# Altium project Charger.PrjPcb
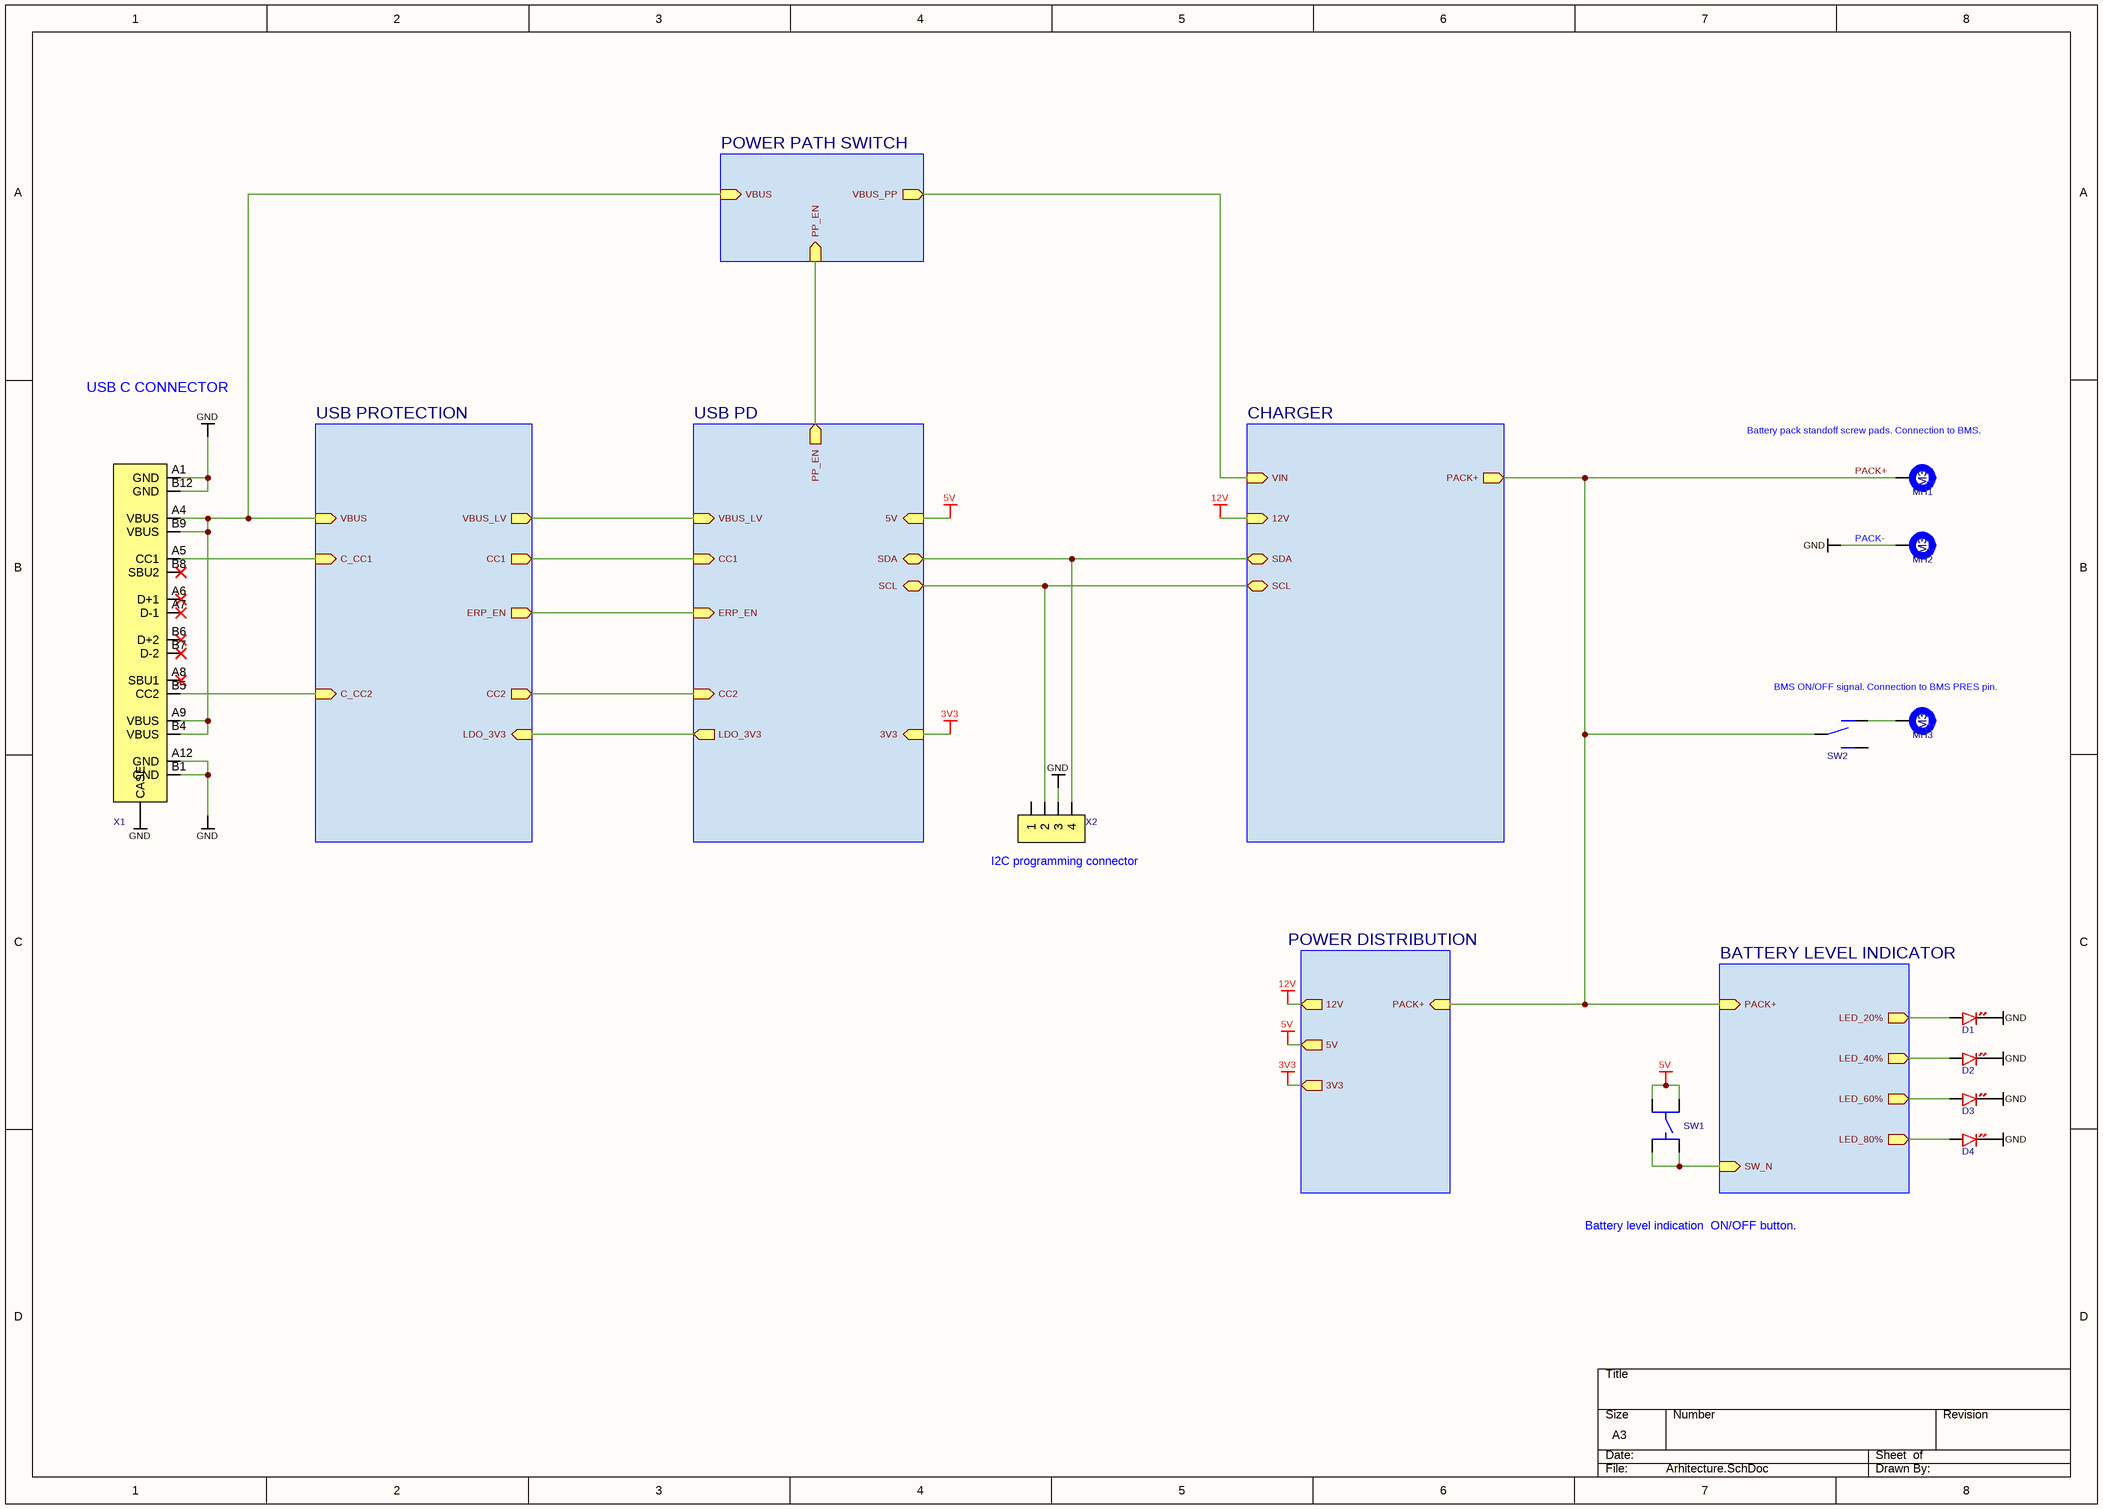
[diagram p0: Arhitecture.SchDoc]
7 sheets, 202 parts. Net scope: hierarchical (ports join the sheet entries above them; power ports are global).
Board file: PCB Charger.PcbDoc
Sheets:
  Arhitecture.SchDoc
    CHARGER = Charger.SchDoc
    POWER DISTRIBUTION = Power distribution.SchDoc
    USB PD = USB PD.SchDoc
    USB PROTECTION = USB protection.SchDoc
    BATTERY LEVEL INDICATOR = Battery level indicator.SchDoc
    POWER PATH SWITCH = Power path switch.SchDoc

## Sheet Arhitecture.SchDoc
size A3; SheetNumber: 1; SheetTotal: 7

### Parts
D1  XL-1608SURC-06  [DIODE_0603]  (value not drawn)
D2  XL-1608SURC-06  [DIODE_0603]  (value not drawn)
D3  XL-1608SURC-06  [DIODE_0603]  (value not drawn)
D4  XL-1608SURC-06  [DIODE_0603]  (value not drawn)
MH1  Hole size: M3  [M3 Plated]  (hidden comment: M?)  (no BOM)
MH2  Hole size: M3  [M3 Plated]  (hidden comment: M?)  (no BOM)
MH3  Hole size: M3  [M3 Plated]  (hidden comment: M?)  (no BOM)
SW1  TS4560TP  [TS4560TP]  (value not drawn)
SW2  SS-3235S-L3  [SS-3235S-L3]  (value not drawn)
X1  TYPE-C 16P LTH6.8  [TYPE-C 16P LTH6.8]  (value not drawn)
X2  B4B-PH-K-S(LF)(SN)  [B4B-PH-K-S(LF)(SN)]  (value not drawn)

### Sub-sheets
BATTERY LEVEL INDICATOR = Battery level indicator.SchDoc: PACK+ (in), SW_N (in), LED_20% (out), LED_40% (out), LED_60% (out), LED_80% (out)
CHARGER = Charger.SchDoc: PACK+ (out), VIN (in), SDA (bidir), SCL (bidir), 12V (in)
POWER DISTRIBUTION = Power distribution.SchDoc: PACK+ (in), 12V (out), 5V (out), 3V3 (out)
POWER PATH SWITCH = Power path switch.SchDoc: VBUS (in), VBUS_PP (out), PP_EN (in)
USB PD = USB PD.SchDoc: VBUS_LV (in), ERP_EN (in), CC1 (in), LDO_3V3 (out), SDA (bidir), SCL (bidir), 5V (in), 3V3 (in), CC2 (in), PP_EN (out)
USB PROTECTION = USB protection.SchDoc: VBUS (in), C_CC1 (in), C_CC2 (in), VBUS_LV (out), ERP_EN (out), CC1 (out), LDO_3V3 (in), CC2 (out)

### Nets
3V3: sheet POWER DISTRIBUTION/3V3, sheet USB PD/3V3
5V: SW1.1 SW1.2 ; sheet POWER DISTRIBUTION/5V, sheet USB PD/5V
5V_SoC: SW1.3 SW1.4 ; sheet BATTERY LEVEL INDICATOR/SW_N
12V: sheet CHARGER/12V, sheet POWER DISTRIBUTION/12V
GND: D1.K D2.K D3.K D4.K MH2.1 X1.A1(GND) X1.A12(GND) X1.B1(GND) X1.B12(GND) X1.CASE X2.3
LDO_3V3: sheet USB PD/LDO_3V3, sheet USB PROTECTION/LDO_3V3
C_CC1: X1.A5(CC1) ; sheet USB PROTECTION/C_CC1
C_CC2: X1.B5(CC2) ; sheet USB PROTECTION/C_CC2
CC1: sheet USB PD/CC1, sheet USB PROTECTION/CC1
CC2: sheet USB PD/CC2, sheet USB PROTECTION/CC2
ERP_EN: sheet USB PD/ERP_EN, sheet USB PROTECTION/ERP_EN
PACK+: MH1.1 SW2.2 ; sheet CHARGER/PACK+, sheet POWER DISTRIBUTION/PACK+, sheet BATTERY LEVEL INDICATOR/PACK+
PP_EN: sheet USB PD/PP_EN, sheet POWER PATH SWITCH/PP_EN
SCL: X2.2 ; sheet CHARGER/SCL, sheet USB PD/SCL
SDA: X2.4 ; sheet CHARGER/SDA, sheet USB PD/SDA
V_CHG_IN: sheet CHARGER/VIN, sheet POWER PATH SWITCH/VBUS_PP
VBUS: X1.A4(VBUS) X1.A9(VBUS) X1.B4(VBUS) X1.B9(VBUS) ; sheet USB PROTECTION/VBUS, sheet POWER PATH SWITCH/VBUS
VBUS_LV: sheet USB PD/VBUS_LV, sheet USB PROTECTION/VBUS_LV
NetD1_A: D1.A ; sheet BATTERY LEVEL INDICATOR/LED_20%
NetD2_A: D2.A ; sheet BATTERY LEVEL INDICATOR/LED_40%
NetD3_A: D3.A ; sheet BATTERY LEVEL INDICATOR/LED_60%
NetD4_A: D4.A ; sheet BATTERY LEVEL INDICATOR/LED_80%
NetMH3_1: MH3.1 SW2.1

Not connected (* = marked no-connect by the designer): SW2 3; X1 A6(D+1)* A7(D-1)* A8(SBU1)* B6(D+2)* B7(D-2)* B8(SBU2)*; X2 1

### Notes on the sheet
- USB C CONNECTOR
- (near MH1) Battery pack standoff screw pads. Connection to BMS.
- (near MH2) PACK-
- BMS ON/OFF signal. Connection to BMS PRES pin.
- (near X2) I2C programming connector
- Battery level indication  ON/OFF button.

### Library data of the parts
D1-D4 = XL-1608SURC-06: LED Red 0603 25mA; Manufacturer: Xinglight
MH1-MH3 = Mounting hole: Generic mounting hole symbol
SW1 = TS4560TP: Switch Tactile SMD 4.5x4.5mm 6mmH SPST; Manufacturer: Shou Han
SW2 = SS-3235S-L3: Switch Slide SMD 9.1x3.5mm 6.6mmH; Manufacturer: XKB Connection
X1 = TYPE-C 16P LTH6.8: USB-C 16P SMD Vertical 6.50mmH; Manufacturer: Shou Han
X2 = B4B-PH-K-S(LF)(SN): Pin header 1x4 2.00mmP THT Vertical JST PH

## Sheet Charger.SchDoc
size A3; SheetNumber: 2; SheetTotal: 3
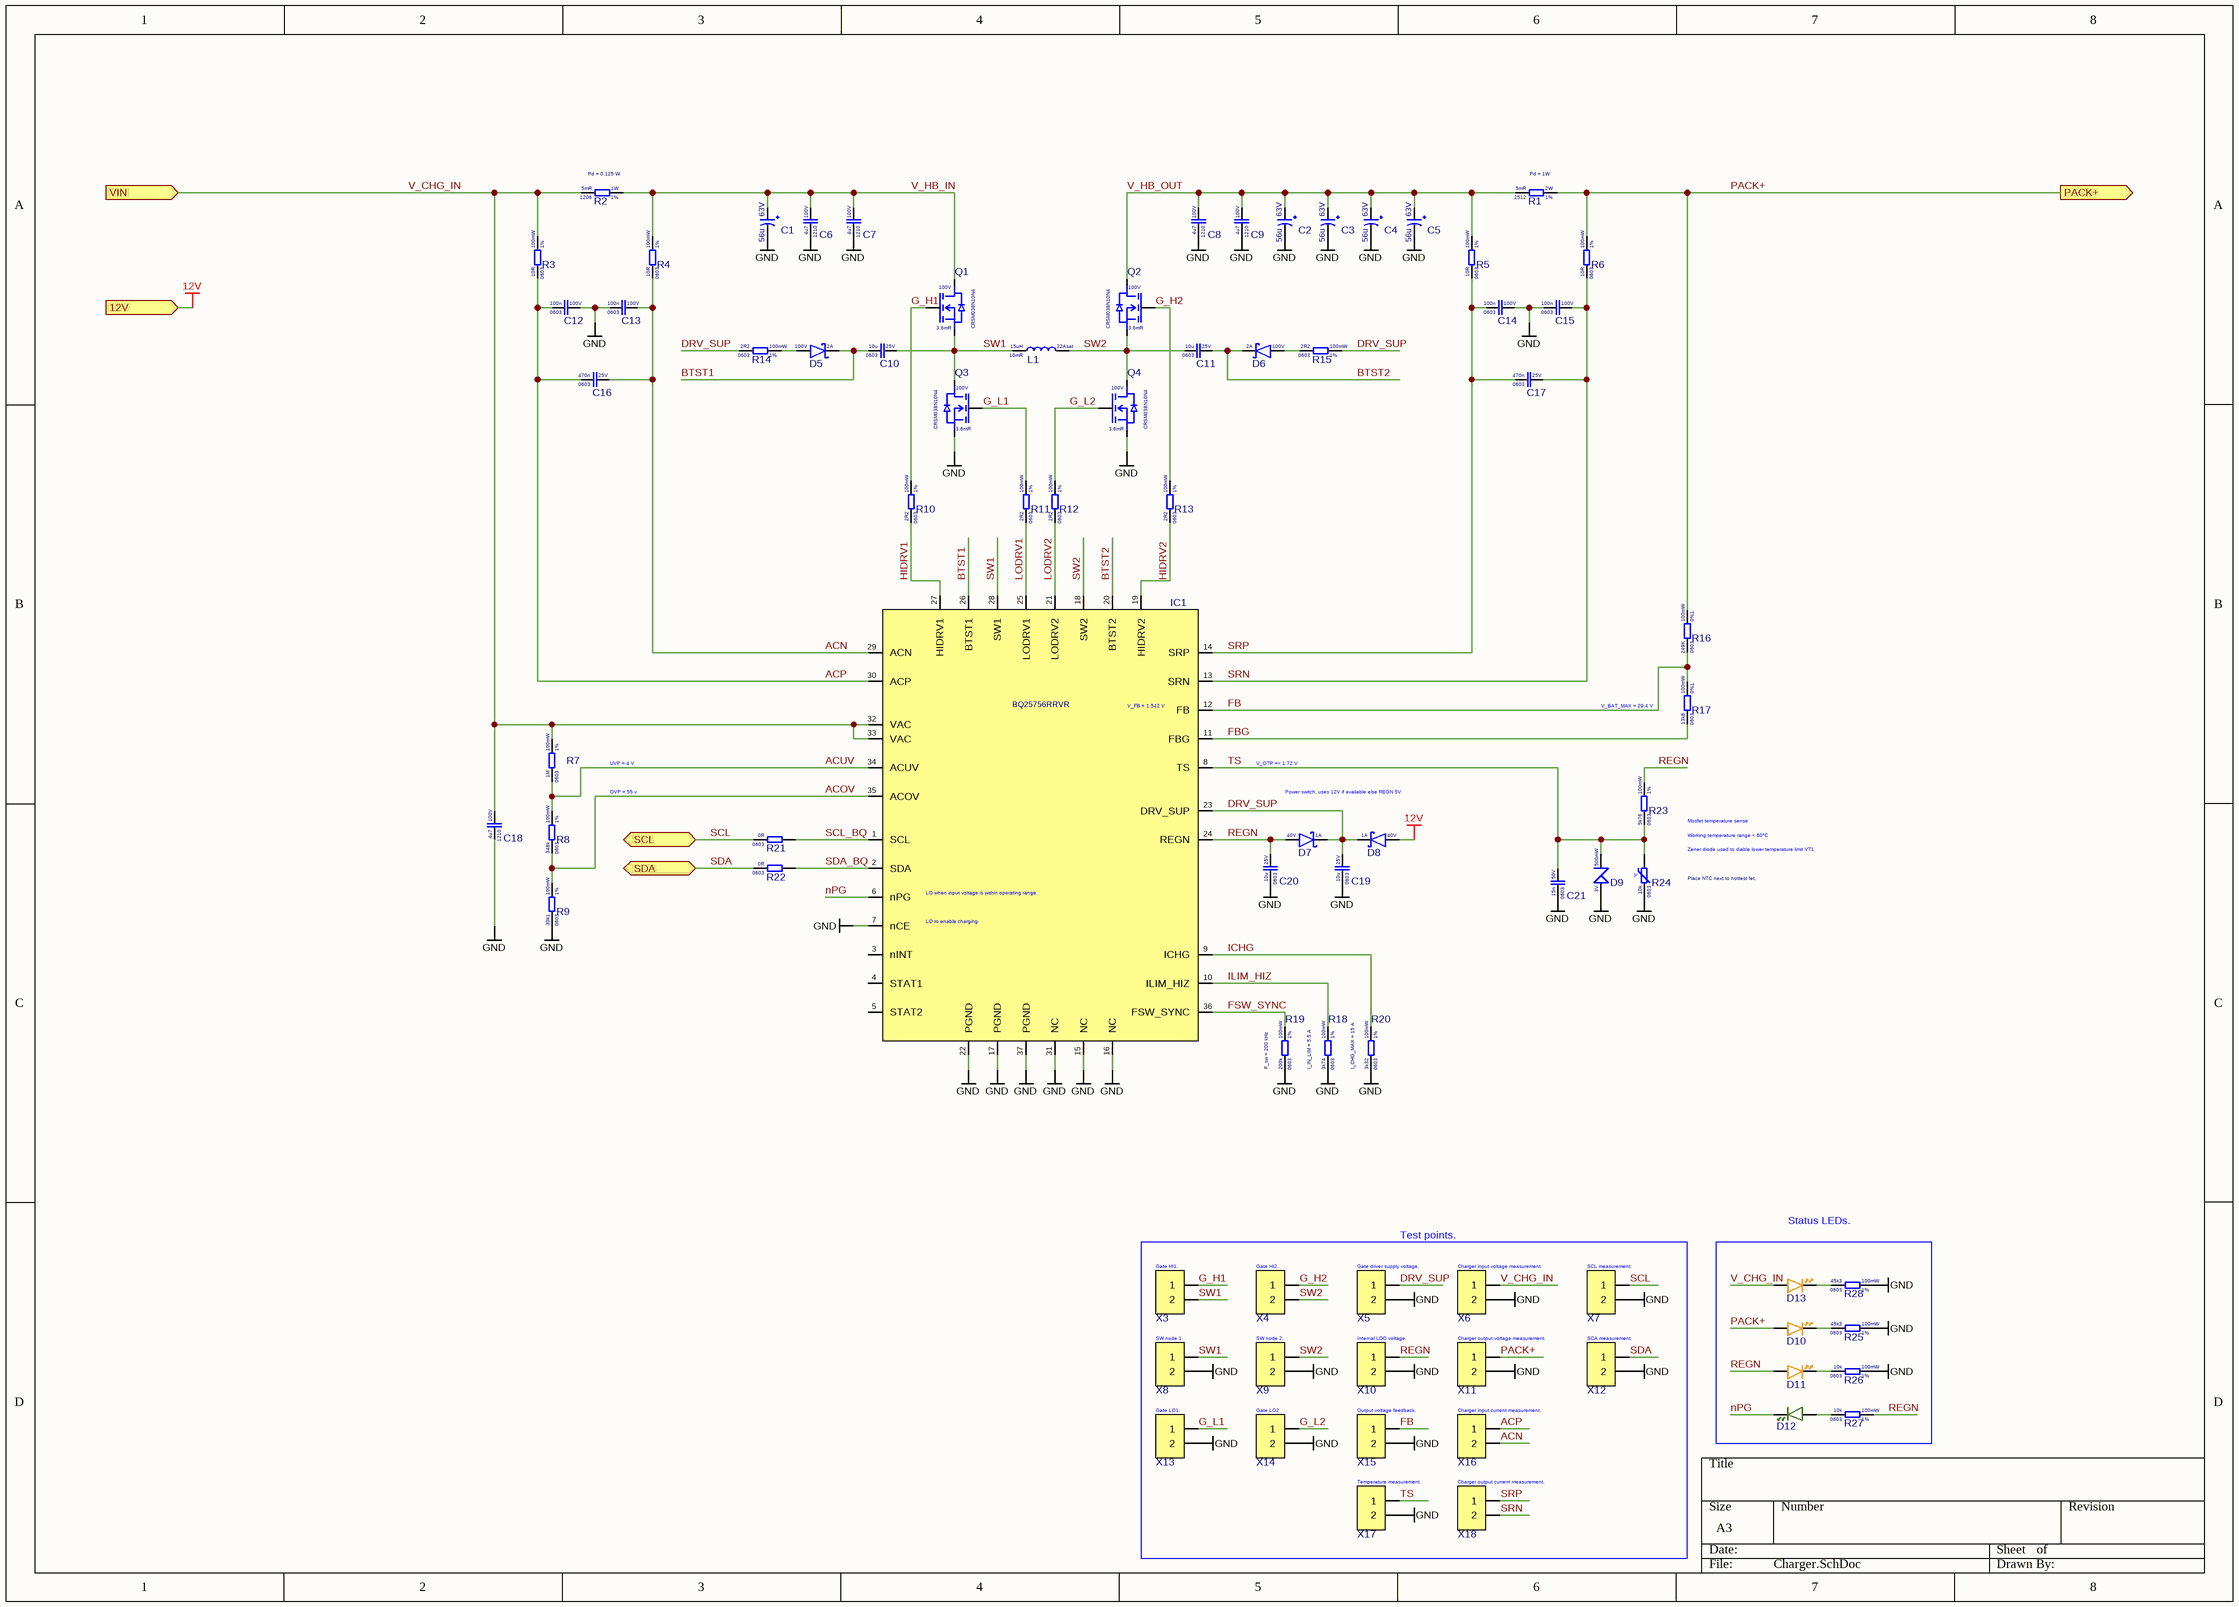
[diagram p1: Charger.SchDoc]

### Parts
C1  Voltage Rating: 63V  Capacitance: 56u  [CAP_SMD_10X10.2]  (hidden comment: EEHZA1J560P)
C2  Voltage Rating: 63V  Capacitance: 56u  [CAP_SMD_10X10.2]  (hidden comment: EEHZA1J560P)
C3  Voltage Rating: 63V  Capacitance: 56u  [CAP_SMD_10X10.2]  (hidden comment: EEHZA1J560P)
C4  Voltage Rating: 63V  Capacitance: 56u  [CAP_SMD_10X10.2]  (hidden comment: EEHZA1J560P)
C5  Voltage Rating: 63V  Capacitance: 56u  [CAP_SMD_10X10.2]  (hidden comment: EEHZA1J560P)
C6  Voltage Rating: 100V  Case Code (Imperial): 1210  Capacitance: 4u7  [CAP_1210]  (hidden comment: HMK325C7475KN-TE)
C7  Voltage Rating: 100V  Case Code (Imperial): 1210  Capacitance: 4u7  [CAP_1210]  (hidden comment: HMK325C7475KN-TE)
C8  Voltage Rating: 100V  Case Code (Imperial): 1210  Capacitance: 4u7  [CAP_1210]  (hidden comment: HMK325C7475KN-TE)
C9  Voltage Rating: 100V  Case Code (Imperial): 1210  Capacitance: 4u7  [CAP_1210]  (hidden comment: HMK325C7475KN-TE)
C10  Voltage Rating: 25V  Case Code (Imperial): 0603  Capacitance: 10u  [CAP 0603]  (hidden comment: CL10A106MA8NRNC)
C11  Voltage Rating: 25V  Case Code (Imperial): 0603  Capacitance: 10u  [CAP 0603]  (hidden comment: CL10A106MA8NRNC)
C12  Voltage Rating: 100V  Case Code (Imperial): 0603  Capacitance: 100n  [CAP 0603]  (hidden comment: CC0603KRX7R0BB104)
C13  Voltage Rating: 100V  Case Code (Imperial): 0603  Capacitance: 100n  [CAP 0603]  (hidden comment: CC0603KRX7R0BB104)
C14  Voltage Rating: 100V  Case Code (Imperial): 0603  Capacitance: 100n  [CAP 0603]  (hidden comment: CC0603KRX7R0BB104)
C15  Voltage Rating: 100V  Case Code (Imperial): 0603  Capacitance: 100n  [CAP 0603]  (hidden comment: CC0603KRX7R0BB104)
C16  Voltage Rating: 25V  Case Code (Imperial): 0603  Capacitance: 470n  [CAP 0603]  (hidden comment: CL10B474KA8NNNC)
C17  Voltage Rating: 25V  Case Code (Imperial): 0603  Capacitance: 470n  [CAP 0603]  (hidden comment: CL10B474KA8NNNC)
C18  Voltage Rating: 100V  Case Code (Imperial): 1210  Capacitance: 4u7  [CAP_1210]  (hidden comment: HMK325C7475KN-TE)
C19  Voltage Rating: 25V  Case Code (Imperial): 0603  Capacitance: 10u  [CAP 0603]  (hidden comment: CL10A106MA8NRNC)
C20  Voltage Rating: 25V  Case Code (Imperial): 0603  Capacitance: 10u  [CAP 0603]  (hidden comment: CL10A106MA8NRNC)
C21  Voltage Rating: 50V  Case Code (Imperial): 0603  Capacitance: 15n  [CAP 0603]  (hidden comment: CC0603KRX7R9BB153)
D5  Forward Current: 2A  Reverse Voltage: 100V  [SMAF]  (hidden comment: SS210F)
D6  Forward Current: 2A  Reverse Voltage: 100V  [SMAF]  (hidden comment: SS210F)
D7  Forward Current: 1A  Reverse Voltage: 40V  [SOD-323]  (hidden comment: 1N5819WS)
D8  Forward Current: 1A  Reverse Voltage: 40V  [SOD-323]  (hidden comment: 1N5819WS)
D9  Power Rating: 500mW  Reverse Voltage: 3V  [SOD-123]  (hidden comment: BZT52C3V0)
D10  XL-1608UOC-06  [DIODE_0603]  (value not drawn)
D11  XL-1608UOC-06  [DIODE_0603]  (value not drawn)
D12  PSC-1608U52GC-G4  [DIODE_0603]  (value not drawn)
D13  XL-1608UOC-06  [DIODE_0603]  (value not drawn)
IC1  BQ25756RRVR  [VQFN-36(5x6)]
L1  Resistance: 10mR  Saturation current: 22Asat  Inductance: 15uH  [MTF1810-150M]  (hidden comment: MTF1810-150M)
Q1  Rds: 3.6mR  Voltage: 100V  [DFN-8 (5x6)]  (hidden comment: CRSM038N10N4)
Q2  Rds: 3.6mR  Voltage: 100V  [DFN-8 (5x6)]  (hidden comment: CRSM038N10N4)
Q3  Rds: 3.6mR  Voltage: 100V  [DFN-8 (5x6)]  (hidden comment: CRSM038N10N4)
Q4  Rds: 3.6mR  Voltage: 100V  [DFN-8 (5x6)]  (hidden comment: CRSM038N10N4)
R1  Pd = 1W  Resistance Tolerance: 1%  Resistance: 5mR  Power Rating: 2W  Case Code (Imperial): 2512  [RES_2512]
R2  Pd = 0.125 W  Resistance Tolerance: 1%  Resistance: 5mR  Power Rating: 1W  Case Code (Imperial): 1206  [RES_1206]
R3  Resistance Tolerance: 1%  Resistance: 10R  Power Rating: 100mW  Case Code (Imperial): 0603  [RES_0603]  (hidden comment: 0603WAF100JT5E)
R4  Resistance Tolerance: 1%  Resistance: 10R  Power Rating: 100mW  Case Code (Imperial): 0603  [RES_0603]  (hidden comment: 0603WAF100JT5E)
R5  Resistance Tolerance: 1%  Resistance: 10R  Power Rating: 100mW  Case Code (Imperial): 0603  [RES_0603]  (hidden comment: 0603WAF100JT5E)
R6  Resistance Tolerance: 1%  Resistance: 10R  Power Rating: 100mW  Case Code (Imperial): 0603  [RES_0603]  (hidden comment: 0603WAF100JT5E)
R7  Resistance Tolerance: 1%  Resistance: 1M  Power Rating: 100mW  Case Code (Imperial): 0603  [RES_0603]  (hidden comment: 0603WAF1004T5E)
R8  Resistance Tolerance: 1%  Resistance: 348k  Power Rating: 100mW  Case Code (Imperial): 0603  [RES_0603]  (hidden comment: 0603WAF3483T5E)
R9  Resistance Tolerance: 1%  Resistance: 30k1  Power Rating: 100mW  Case Code (Imperial): 0603  [RES_0603]  (hidden comment: 0603WAF3012T5E)
R10  Resistance Tolerance: 1%  Resistance: 2R2  Power Rating: 100mW  Case Code (Imperial): 0603  [RES_0603]  (hidden comment: 0603WAF220KT5E)
R11  Resistance Tolerance: 1%  Resistance: 2R2  Power Rating: 100mW  Case Code (Imperial): 0603  [RES_0603]  (hidden comment: 0603WAF220KT5E)
R12  Resistance Tolerance: 1%  Resistance: 2R2  Power Rating: 100mW  Case Code (Imperial): 0603  [RES_0603]  (hidden comment: 0603WAF220KT5E)
R13  Resistance Tolerance: 1%  Resistance: 2R2  Power Rating: 100mW  Case Code (Imperial): 0603  [RES_0603]  (hidden comment: 0603WAF220KT5E)
R14  Resistance Tolerance: 1%  Resistance: 2R2  Power Rating: 100mW  Case Code (Imperial): 0603  [RES_0603]  (hidden comment: 0603WAF220KT5E)
R15  Resistance Tolerance: 1%  Resistance: 2R2  Power Rating: 100mW  Case Code (Imperial): 0603  [RES_0603]  (hidden comment: 0603WAF220KT5E)
R16  Resistance Tolerance: 0%1  Resistance: 249K  Power Rating: 100mW  Case Code (Imperial): 0603  [RES_0603]  (hidden comment: RT0603BRD07249KL)
R17  Resistance Tolerance: 0%1  Resistance: 13k8  Power Rating: 100mW  Case Code (Imperial): 0603  [RES_0603]  (hidden comment: RT0603BRD0713K8L)
R18  I_IN_LIM = 5.5 A  Resistance Tolerance: 1%  Resistance: 3k74  Power Rating: 100mW  Case Code (Imperial): 0603  [RES_0603]
R19  F_sw = 200 kHz  Resistance Tolerance: 1%  Resistance: 200k  Power Rating: 100mW  Case Code (Imperial): 0603  [RES_0603]
R20  I_CHG_MAX = 15 A  Resistance Tolerance: 1%  Resistance: 3k32  Power Rating: 100mW  Case Code (Imperial): 0603  [RES_0603]
R21  Resistance: 0R  Case Code (Imperial): 0603  [RES_0603]  (hidden comment: 0603WAF0000T5E)
R22  Resistance: 0R  Case Code (Imperial): 0603  [RES_0603]  (hidden comment: 0603WAF0000T5E)
R23  Resistance Tolerance: 1%  Resistance: 5k76  Power Rating: 100mW  Case Code (Imperial): 0603  [RES_0603]  (hidden comment: 0603WAF5761T5E)
R24  Place NTC next to hottest fet.  Resistance: 10k  Case Code (Imperial): 0603  [RES_0603]
R25  Resistance Tolerance: 1%  Resistance: 45k3  Power Rating: 100mW  Case Code (Imperial): 0603  [RES_0603]  (hidden comment: 0603WAF4532T5E)
R26  Resistance Tolerance: 1%  Resistance: 10k  Power Rating: 100mW  Case Code (Imperial): 0603  [RES_0603]  (hidden comment: 0603WAF1002T5E)
R27  Resistance Tolerance: 1%  Resistance: 10k  Power Rating: 100mW  Case Code (Imperial): 0603  [RES_0603]  (hidden comment: 0603WAF1002T5E)
R28  Resistance Tolerance: 1%  Resistance: 45k3  Power Rating: 100mW  Case Code (Imperial): 0603  [RES_0603]  (hidden comment: 0603WAF4532T5E)
X3  ZX-PZ1.27-1-2PZZ  [Pin header 1x2 1.27mmP THT Vertical]  (value not drawn)
X4  ZX-PZ1.27-1-2PZZ  [Pin header 1x2 1.27mmP THT Vertical]  (value not drawn)
X5  ZX-PZ1.27-1-2PZZ  [Pin header 1x2 1.27mmP THT Vertical]  (value not drawn)
X6  ZX-PZ1.27-1-2PZZ  [Pin header 1x2 1.27mmP THT Vertical]  (value not drawn)
X7  ZX-PZ1.27-1-2PZZ  [Pin header 1x2 1.27mmP THT Vertical]  (value not drawn)
X8  ZX-PZ1.27-1-2PZZ  [Pin header 1x2 1.27mmP THT Vertical]  (value not drawn)
X9  ZX-PZ1.27-1-2PZZ  [Pin header 1x2 1.27mmP THT Vertical]  (value not drawn)
X10  ZX-PZ1.27-1-2PZZ  [Pin header 1x2 1.27mmP THT Vertical]  (value not drawn)
X11  ZX-PZ1.27-1-2PZZ  [Pin header 1x2 1.27mmP THT Vertical]  (value not drawn)
X12  ZX-PZ1.27-1-2PZZ  [Pin header 1x2 1.27mmP THT Vertical]  (value not drawn)
X13  ZX-PZ1.27-1-2PZZ  [Pin header 1x2 1.27mmP THT Vertical]  (value not drawn)
X14  ZX-PZ1.27-1-2PZZ  [Pin header 1x2 1.27mmP THT Vertical]  (value not drawn)
X15  ZX-PZ1.27-1-2PZZ  [Pin header 1x2 1.27mmP THT Vertical]  (value not drawn)
X16  ZX-PZ1.27-1-2PZZ  [Pin header 1x2 1.27mmP THT Vertical]  (value not drawn)
X17  ZX-PZ1.27-1-2PZZ  [Pin header 1x2 1.27mmP THT Vertical]  (value not drawn)
X18  ZX-PZ1.27-1-2PZZ  [Pin header 1x2 1.27mmP THT Vertical]  (value not drawn)

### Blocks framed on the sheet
Test points.: X3-X18
Status LEDs.: D10-D13 R25-R28

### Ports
12V (in, see Arhitecture[5B]), PACK+ (out, see Arhitecture[6B], Battery level indicator[3B]), SCL (bidir, see Arhitecture[5B]), SDA (bidir, see Arhitecture[5B]), VIN (in, see Arhitecture[5B])

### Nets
12V: D8.A ; port 12V
GND: C1.- C2.- C3.- C4.- C5.- C6.1 C7.1 C8.1 C9.1 C12.2 C13.1 C14.2 C15.1 C18.1 C19.1 C20.1 C21.1 D9.A IC1.7(nCE) IC1.15(NC) IC1.16(NC) IC1.17(PGND) IC1.22(PGND) IC1.31(NC) IC1.37(PGND) Q3.S Q4.S R9.1 R18.1 R19.1 R20.1 R24.1 R25.2 R26.2 R28.2 X5.2 X6.2 X7.2 X8.2 X9.2 X10.2 X11.2 X12.2 X13.2 X14.2 X15.2 X17.2
ACN: C13.2 C16.2 IC1.29(ACN) R4.1 X16.2
ACOV: IC1.35(ACOV) R8.1 R9.2
ACP: C12.1 C16.1 IC1.30(ACP) R3.1 X16.1
ACUV: IC1.34(ACUV) R7.1 R8.2
BTST1: C10.1 D5.K IC1.26(BTST1)
BTST2: C11.2 D6.K IC1.20(BTST2)
DRV_SUP: C19.2 D7.K D8.K IC1.23(DRV_SUP) R14.1 R15.2 X5.1
FB: IC1.12(FB) R16.1 R17.2 X15.1
FBG: IC1.11(FBG) R17.1
FSW_SYNC: IC1.36(FSW_SYNC) R19.2
G_H1: Q1.G R10.2 X3.1
G_H2: Q2.G R13.2 X4.1
G_L1: Q3.G R11.2 X13.1
G_L2: Q4.G R12.2 X14.1
HIDRV1: IC1.27(HIDRV1) R10.1
HIDRV2: IC1.19(HIDRV2) R13.1
ICHG: IC1.9(ICHG) R20.2
ILIM_HIZ: IC1.10(ILIM_HIZ) R18.2
LODRV1: IC1.25(LODRV1) R11.1
LODRV2: IC1.21(LODRV2) R12.1
nPG: D12.K IC1.6(nPG)
PACK+: D10.A R1.2 R6.2 R16.2 X11.1 ; port PACK+
REGN: C20.2 D7.A D11.A IC1.24(REGN) R23.2 R27.2 X10.1
SCL: R21.1 X7.1 ; port SCL
SCL_BQ: IC1.1(SCL) R21.2
SDA: R22.1 X12.1 ; port SDA
SDA_BQ: IC1.2(SDA) R22.2
SRN: C15.2 C17.2 IC1.13(SRN) R6.1 X18.2
SRP: C14.1 C17.1 IC1.14(SRP) R5.1 X18.1
SW1: C10.2 IC1.28(SW1) L1.1 Q1.S Q3.D X3.2 X8.1
SW2: C11.1 IC1.18(SW2) L1.2 Q2.S Q4.D X4.2 X9.1
TS: C21.2 D9.K IC1.8(TS) R23.1 R24.2 X17.1
V_CHG_IN: C18.2 D13.A IC1.32(VAC) IC1.33(VAC) R2.1 R3.2 R7.2 X6.1 ; port VIN
V_HB_IN: C1.+ C6.2 C7.2 Q1.D R2.2 R4.2
V_HB_OUT: C2.+ C3.+ C4.+ C5.+ C8.2 C9.2 Q2.D R1.1 R5.2
NetD5_A: D5.A R14.2
NetD6_A: D6.A R15.1
NetD10_K: D10.K R25.1
NetD11_K: D11.K R26.1
NetD12_A: D12.A R27.1
NetD13_K: D13.K R28.1

Not connected (* = marked no-connect by the designer): IC1 3(nINT) 4(STAT1) 5(STAT2)

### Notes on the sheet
- UVP = 4 V
- (near IC1) V_FB = 1.542 V
- V_OTP =< 1.72 V
- (near R17) V_BAT_MAX = 29.4 V
- OVP = 55 v
- Power switch, uses 12V if available else REGN 5V.
- Mosfet temperature sense
- Working temperature range < 60°C
- (near IC1) LO when input voltage is within operating range.
- Zener diode used to diable lower temperature limit VT1.
- (near IC1) LO to enable charging.
- (near X3) Gate HI1.
- (near X4) Gate HI2.
- (near X5) Gate driver supply voltage.
- (near X6) Charger input voltage measurement.
- (near X7) SCL measurement.
- (near X8) SW node 1.
- (near X9) SW node 2.
- (near X10) Internal LDO voltage.
- (near X11) Charger output voltage measurement.
- (near X12) SCA measurement.
- (near X13) Gate LO1.
- (near X14) Gate LO2
- (near X15) Output voltage feedback.
- (near X16) Charger input current measurement.
- (near X17) Temperature measurement.
- (near X18) Charger output current measurement.

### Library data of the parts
C1-C5 = EEHZA1J560P: Cap AL-EL 56uF 63V 30mR 1.8Ar SMD 10x10.2mm; Manufacturer: Panasonic
C6-C9 C18 = HMK325C7475KN-TE: Cap 4.7uF 100V 1210 X7R; Manufacturer: Taiyo Yuden
C10 C11 C19 C20 = CL10A106MA8NRNC: Cap 10uF 25V 0603 X5R; Manufacturer: Samsung
C12-C15 = CC0603KRX7R0BB104: Cap 100nF 100V 0603 X7R; Manufacturer: YAGEO
C16 C17 = CL10B474KA8NNNC: Cap 470nF 25V 0603 X7R; Manufacturer: Samsung
C21 = CC0603KRX7R9BB153: Cap 15nF 50V 0603 X7R; Manufacturer: Yageo; Manufacturer Part Number: CC0603KRX7R9BB104
D5 D6 = SS210F: Schottky 100V 2A 850mVf SMAF; Manufacturer: GOODWORK
D7 D8 = 1N5819WS: Schottky 40V 1A 600mVf SOD-323; Manufacturer: Guangdong Hottech
D9 = BZT52C3V0: Zener 3.0V 500mW SOD-123; Manufacturer: Shandong Jingdao Microelectronics
D10 D11 D13 = XL-1608UOC-06: LED Orange 0603 20mA; Manufacturer: XINGLIGHT
D12 = PSC-1608U52GC-G4: LED Green 0603 20mA; Manufacturer: HONGLITRONIC
IC1 = BQ25756RRVR: Charger IC; Manufacturer: Texas Instruments
L1 = MTF1810-150M: Inductor 15uH 22Asat 10mR SMD 18x18x9 mm; Manufacturer: COILMX
Q1-Q4 = CRSM038N10N4: Nmos 100V 100A 3.6mR DFN-8(5x6); Manufacturer: CRMICRO
R1 = RLM25FEER005: Res 5mR 2512 1% 2W; Manufacturer: TA-I Tech
R2 = FRM121WFR005TM: Res 5mR 1206 1% 1W; Manufacturer: FOJAN
R3-R6 = 0603WAF100JT5E: Res 10R 0603 1% 100mW 75V; Manufacturer: Uni-Royal
R7 = 0603WAF1004T5E: Res 1M 0603 1% 100mW 75V; Manufacturer: Uni-Royal
R8 = 0603WAF3483T5E: Res 348k 0603 1% 100mW 75V; Manufacturer: Uni-Royal
R9 = 0603WAF3012T5E: Res 30k1 0603 1% 100mW 75V; Manufacturer: Uni-Royal
R10-R15 = 0603WAF220KT5E: Res 2R2 0603 1% 100mW 75V; Manufacturer: Uni-Royal
R16 = RT0603BRD07249KL: Res 249K 0603 0.1% 100mW 75V; Manufacturer: YAGEO
R17 = RT0603BRD0713K8L: Res 13.8k 0603 0.1% 100mW 75V; Manufacturer: YAGEO
R18 = FRC0603F3741TS: Res 3K74 0603 1% 100mW 75V; Manufacturer: FOJAN
R19 = 0603WAF2003T5E: Res 200K 0603 1% 100mW 75V; Manufacturer: UNI-ROYAL
R20 = 0603WAF3321T5E: Res 3k32 0603 1% 100mW 75V; Manufacturer: UNI-ROYAL
R21 R22 = 0603WAF0000T5E: Res 0R 0603 1% 100mW 75V; Manufacturer: UNI-ROYAL
R23 = 0603WAF5761T5E: Res 5k76 0603 1% 100mW 75V; Manufacturer: Uni-Royal
R24 = NCP18XH103F03RB: NTC 10k 0603 1% 3455K; Manufacturer: Murata
R25 R28 = 0603WAF4532T5E: Res 45k3 0603 1% 100mW 75V; Manufacturer: Uni-Royal
R26 R27 = 0603WAF1002T5E: Res 10k 0603 1% 100mW 75V; Manufacturer: Uni-Royal
X3-X18 = ZX-PZ1.27-1-2PZZ: Pin header 1x2 1.27mmP THT Vertical; Manufacturer: Megastar

## Sheet Power distribution.SchDoc
size A3; SheetNumber: 4; SheetTotal: 7
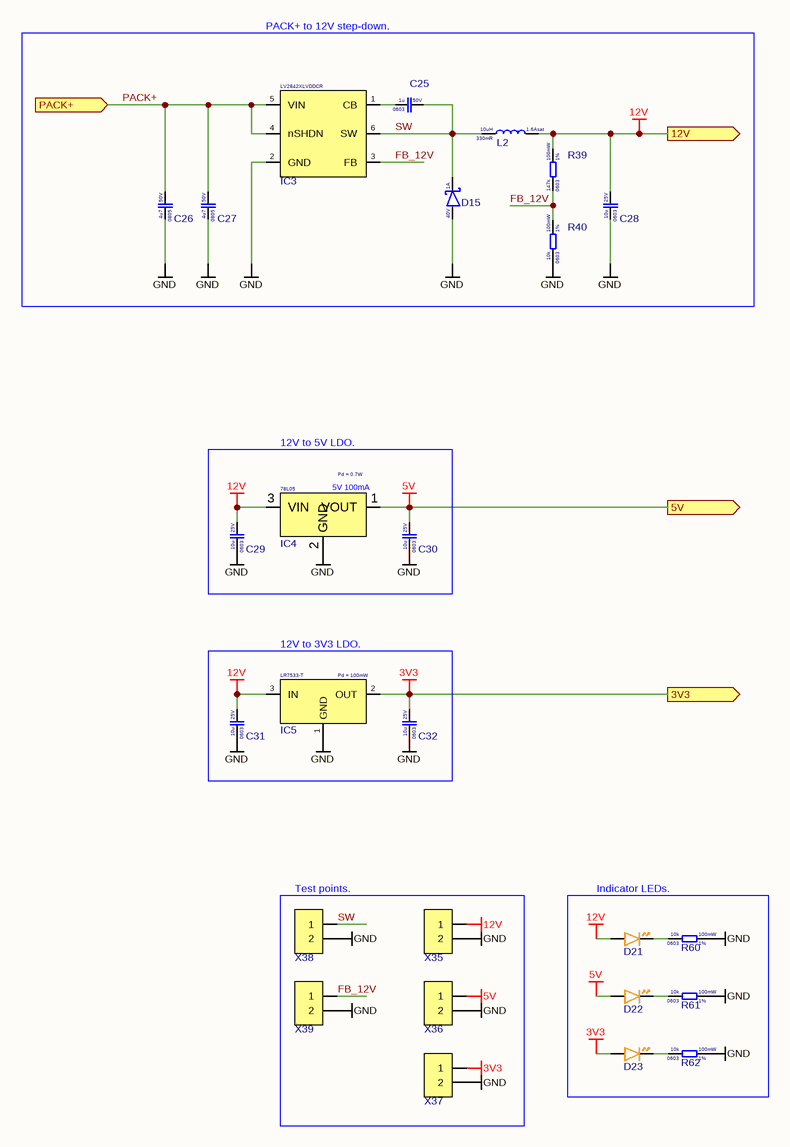
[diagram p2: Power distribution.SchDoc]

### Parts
C25  Voltage Rating: 50V  Case Code (Imperial): 0603  Capacitance: 1u  [CAP 0603]  (hidden comment: CL10A105KB8NNNC)
C26  Voltage Rating: 50V  Case Code (Imperial): 0805  Capacitance: 4u7  [Cap_0805]  (hidden comment: CL21A475KBQNNNE)
C27  Voltage Rating: 50V  Case Code (Imperial): 0805  Capacitance: 4u7  [Cap_0805]  (hidden comment: CL21A475KBQNNNE)
C28  Voltage Rating: 25V  Case Code (Imperial): 0603  Capacitance: 10u  [CAP 0603]  (hidden comment: CL10A106MA8NRNC)
C29  Voltage Rating: 25V  Case Code (Imperial): 0603  Capacitance: 10u  [CAP 0603]  (hidden comment: CL10A106MA8NRNC)
C30  Voltage Rating: 25V  Case Code (Imperial): 0603  Capacitance: 10u  [CAP 0603]  (hidden comment: CL10A106MA8NRNC)
C31  Voltage Rating: 25V  Case Code (Imperial): 0603  Capacitance: 10u  [CAP 0603]  (hidden comment: CL10A106MA8NRNC)
C32  Voltage Rating: 25V  Case Code (Imperial): 0603  Capacitance: 10u  [CAP 0603]  (hidden comment: CL10A106MA8NRNC)
D15  Forward Current: 1A  Reverse Voltage: 40V  [SOD-323]  (hidden comment: 1N5819WS)
D21  XL-1608UOC-06  [DIODE_0603]  (value not drawn)
D22  XL-1608UOC-06  [DIODE_0603]  (value not drawn)
D23  XL-1608UOC-06  [DIODE_0603]  (value not drawn)
IC3  LV2842XLVDDCR  [SOT-23-6]
IC4  Pd = 0.7W  [SOT-89-3]
IC5  Pd = 100mW  [SOT-23 123]
L2  Resistance: 330mR  Saturation current: 1.6Asat  Inductance: 10uH  [IND 1008]  (hidden comment: FTC252012S100MBCA)
R39  Resistance Tolerance: 1%  Resistance: 147k  Power Rating: 100mW  Case Code (Imperial): 0603  [RES_0603]  (hidden comment: 0603WAF1473T5E)
R40  Resistance Tolerance: 1%  Resistance: 10k  Power Rating: 100mW  Case Code (Imperial): 0603  [RES_0603]  (hidden comment: 0603WAF1002T5E)
R60  Resistance Tolerance: 1%  Resistance: 10k  Power Rating: 100mW  Case Code (Imperial): 0603  [RES_0603]  (hidden comment: 0603WAF1002T5E)
R61  Resistance Tolerance: 1%  Resistance: 10k  Power Rating: 100mW  Case Code (Imperial): 0603  [RES_0603]  (hidden comment: 0603WAF1002T5E)
R62  Resistance Tolerance: 1%  Resistance: 10k  Power Rating: 100mW  Case Code (Imperial): 0603  [RES_0603]  (hidden comment: 0603WAF1002T5E)
X35  ZX-PZ1.27-1-2PZZ  [Pin header 1x2 1.27mmP THT Vertical]  (value not drawn)
X36  ZX-PZ1.27-1-2PZZ  [Pin header 1x2 1.27mmP THT Vertical]  (value not drawn)
X37  ZX-PZ1.27-1-2PZZ  [Pin header 1x2 1.27mmP THT Vertical]  (value not drawn)
X38  ZX-PZ1.27-1-2PZZ  [Pin header 1x2 1.27mmP THT Vertical]  (value not drawn)
X39  ZX-PZ1.27-1-2PZZ  [Pin header 1x2 1.27mmP THT Vertical]  (value not drawn)

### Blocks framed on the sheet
PACK+ to 12V step-down.: C25-C28 D15 IC3 L2 R39 R40
12V to 5V LDO.: C29 C30 IC4
12V to 3V3 LDO.: C31 C32 IC5
Test points.: X35-X39
Indicator LEDs.: D21-D23 R60-R62

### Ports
3V3 (out, see Arhitecture[5C], USB PD[3B]), 5V (out, see Arhitecture[5C], USB PD[6B]), 12V (out, see Arhitecture[5C], Charger[1A]), PACK+ (in, see Arhitecture[6C], Battery level indicator[3B], Charger[8A])

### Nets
3V3: C32.2 D23.A IC5.2(OUT) X37.1 ; port 3V3
5V: C30.2 D22.A IC4.1(VOUT) X36.1 ; port 5V
12V: C28.2 C29.2 C31.2 D21.A IC4.3(VIN) IC5.3(IN) L2.2 R39.2 X35.1 ; port 12V
GND: C26.1 C27.1 C28.1 C29.1 C30.1 C31.1 C32.1 D15.A IC3.2(GND) IC4.2(GND) IC5.1(GND) R40.1 R60.2 R61.2 R62.2 X35.2 X36.2 X37.2 X38.2 X39.2
FB_12V: IC3.3(FB) R39.1 R40.2 X39.1
PACK+: C26.2 C27.2 IC3.4(nSHDN) IC3.5(VIN) ; port PACK+
SW: C25.2 D15.K IC3.6(SW) L2.1 X38.1
NetC25_1: C25.1 IC3.1(CB)
NetD21_K: D21.K R60.1
NetD22_K: D22.K R61.1
NetD23_K: D23.K R62.1

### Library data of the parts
C25 = CL10A105KB8NNNC: Cap 1uF 50V 0603 X5R; Manufacturer: Samsung
C26 C27 = CL21A475KBQNNNE: Cap 4.7uF 50V 0805 X5R; Manufacturer: Samsung
C28-C32 = CL10A106MA8NRNC: as C10 on sheet Charger
D15 = 1N5819WS: as D7 on sheet Charger
D21-D23 = XL-1608UOC-06: as D10 on sheet Charger
IC3 = LV2842XLVDDCR: Step-down converter 4~40Vin 600mAout Adjustible SOT23-6; Manufacturer: Texas Instruments
IC4 = 78L05: LDO 5V 100mA 30Vin; Manufacturer: UMW
IC5 = LR7533-T: LDO 24Vin 3.3Vout fixed; Manufacturer: LR
L2 = FTC252012S100MBCA: Inductor 10uH 1.6Asat 330mR; Manufacturer: cjiang
R39 = 0603WAF1473T5E: Res 147k 0603 1% 100mW 75V; Manufacturer: Uni-Royal
R40 R60-R62 = 0603WAF1002T5E: as R26 on sheet Charger
X35-X39 = ZX-PZ1.27-1-2PZZ: as X3 on sheet Charger

## Sheet USB PD.SchDoc
size A3; SheetNumber: 5; SheetTotal: 7
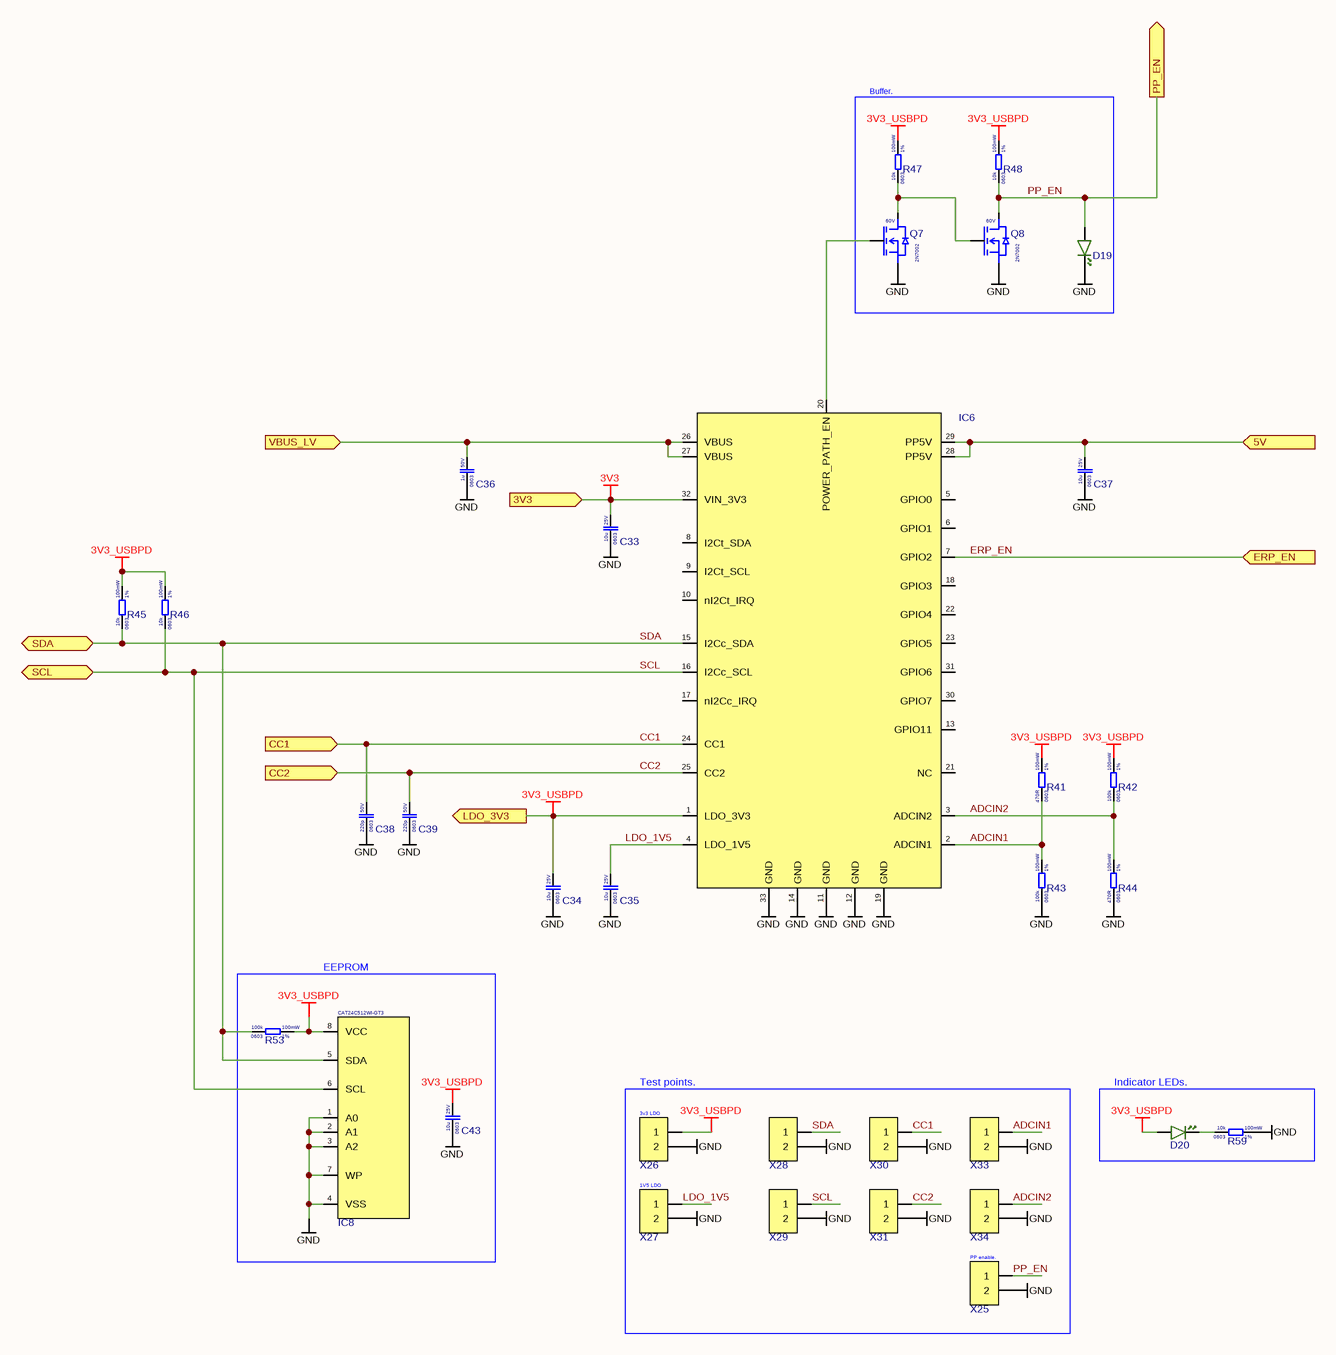
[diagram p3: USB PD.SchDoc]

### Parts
C33  Voltage Rating: 25V  Case Code (Imperial): 0603  Capacitance: 10u  [CAP 0603]  (hidden comment: CL10A106MA8NRNC)
C34  Voltage Rating: 25V  Case Code (Imperial): 0603  Capacitance: 10u  [CAP 0603]  (hidden comment: CL10A106MA8NRNC)
C35  Voltage Rating: 25V  Case Code (Imperial): 0603  Capacitance: 10u  [CAP 0603]  (hidden comment: CL10A106MA8NRNC)
C36  Voltage Rating: 50V  Case Code (Imperial): 0603  Capacitance: 1u  [CAP 0603]  (hidden comment: CL10A105KB8NNNC)
C37  Voltage Rating: 25V  Case Code (Imperial): 0603  Capacitance: 10u  [CAP 0603]  (hidden comment: CL10A106MA8NRNC)
C38  Voltage Rating: 50V  Case Code (Imperial): 0603  Capacitance: 220p  [CAP 0603]  (hidden comment: CL10B221KB8NNNC)
C39  Voltage Rating: 50V  Case Code (Imperial): 0603  Capacitance: 220p  [CAP 0603]  (hidden comment: CL10B221KB8NNNC)
C43  Voltage Rating: 25V  Case Code (Imperial): 0603  Capacitance: 10u  [CAP 0603]  (hidden comment: CL10A106MA8NRNC)
D19  PSC-1608U52GC-G4  [DIODE_0603]  (value not drawn)
D20  Diode LED Green  [DIODE_0603]  (value not drawn)
IC6  TPS26750SRSMR  [VQFN (32) 4x4]  (value not drawn)
IC8  CAT24C512WI-GT3  [SOIC8]
Q7  Voltage: 60V  [SOT-23 GSD]  (hidden comment: 2N7002)
Q8  Voltage: 60V  [SOT-23 GSD]  (hidden comment: 2N7002)
R41  Resistance Tolerance: 1%  Resistance: 470R  Power Rating: 100mW  Case Code (Imperial): 0603  [RES_0603]  (hidden comment: 0603WAF4700T5E)
R42  Resistance Tolerance: 1%  Resistance: 100k  Power Rating: 100mW  Case Code (Imperial): 0603  [RES_0603]  (hidden comment: 0603WAF1003T5E)
R43  Resistance Tolerance: 1%  Resistance: 100k  Power Rating: 100mW  Case Code (Imperial): 0603  [RES_0603]  (hidden comment: 0603WAF1003T5E)
R44  Resistance Tolerance: 1%  Resistance: 470R  Power Rating: 100mW  Case Code (Imperial): 0603  [RES_0603]  (hidden comment: 0603WAF4700T5E)
R45  Resistance Tolerance: 1%  Resistance: 10k  Power Rating: 100mW  Case Code (Imperial): 0603  [RES_0603]  (hidden comment: 0603WAF1002T5E)
R46  Resistance Tolerance: 1%  Resistance: 10k  Power Rating: 100mW  Case Code (Imperial): 0603  [RES_0603]  (hidden comment: 0603WAF1002T5E)
R47  Resistance Tolerance: 1%  Resistance: 10k  Power Rating: 100mW  Case Code (Imperial): 0603  [RES_0603]  (hidden comment: 0603WAF1002T5E)
R48  Resistance Tolerance: 1%  Resistance: 10k  Power Rating: 100mW  Case Code (Imperial): 0603  [RES_0603]  (hidden comment: 0603WAF1002T5E)
R53  Resistance Tolerance: 1%  Resistance: 100k  Power Rating: 100mW  Case Code (Imperial): 0603  [RES_0603]  (hidden comment: 0603WAF1003T5E)
R59  Resistance Tolerance: 1%  Resistance: 10k  Power Rating: 100mW  Case Code (Imperial): 0603  [RES_0603]  (hidden comment: 0603WAF1002T5E)
X25  ZX-PZ1.27-1-2PZZ  [Pin header 1x2 1.27mmP THT Vertical]  (value not drawn)
X26  ZX-PZ1.27-1-2PZZ  [Pin header 1x2 1.27mmP THT Vertical]  (value not drawn)
X27  ZX-PZ1.27-1-2PZZ  [Pin header 1x2 1.27mmP THT Vertical]  (value not drawn)
X28  ZX-PZ1.27-1-2PZZ  [Pin header 1x2 1.27mmP THT Vertical]  (value not drawn)
X29  ZX-PZ1.27-1-2PZZ  [Pin header 1x2 1.27mmP THT Vertical]  (value not drawn)
X30  ZX-PZ1.27-1-2PZZ  [Pin header 1x2 1.27mmP THT Vertical]  (value not drawn)
X31  ZX-PZ1.27-1-2PZZ  [Pin header 1x2 1.27mmP THT Vertical]  (value not drawn)
X33  ZX-PZ1.27-1-2PZZ  [Pin header 1x2 1.27mmP THT Vertical]  (value not drawn)
X34  ZX-PZ1.27-1-2PZZ  [Pin header 1x2 1.27mmP THT Vertical]  (value not drawn)

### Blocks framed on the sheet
Buffer.: D19 Q7 Q8 R47 R48
EEPROM: C43 IC8 R53
Test points.: X25-X31 X33 X34
Indicator LEDs.: D20 R59

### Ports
3V3 (in, see Arhitecture[4B], Power distribution[5D]), 5V (in, see Arhitecture[4B], Power distribution[5C]), CC1 (in, see Arhitecture[3B], USB protection[5B]), CC2 (in, see Arhitecture[3B], USB protection[5B]), ERP_EN (in, see Arhitecture[3B], USB protection[5C]), LDO_3V3 (out, see Arhitecture[3B], USB protection[5B]), PP_EN (out, see Arhitecture[4B], Power path switch[3C]), SCL (bidir, see Arhitecture[4B], Charger[3C]), SDA (bidir, see Arhitecture[4B], Charger[3C]), VBUS_LV (in, see Arhitecture[3B], USB protection[5B])

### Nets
3V3: C33.2 IC6.32(VIN_3V3) ; port 3V3
3V3_USBPD: C34.2 C43.2 D20.A IC6.1(LDO_3V3) IC8.8(VCC) R41.2 R42.2 R45.2 R46.2 R47.2 R48.2 R53.2 X26.1 ; port LDO_3V3  [project net LDO_3V3]
5V: C37.2 IC6.28(PP5V) IC6.29(PP5V) ; port 5V
GND: C33.1 C34.1 C35.1 C36.1 C37.1 C38.1 C39.1 C43.1 D19.K IC6.11(GND) IC6.12(GND) IC6.14(GND) IC6.19(GND) IC6.33(GND) IC8.1(A0) IC8.2(A1) IC8.3(A2) IC8.4(VSS) IC8.7(WP) Q7.S Q8.S R43.1 R44.1 R59.2 X25.2 X26.2 X27.2 X28.2 X29.2 X30.2 X31.2 X33.2 X34.2
ADCIN1: IC6.2(ADCIN1) R41.1 R43.2 X33.1
ADCIN2: IC6.3(ADCIN2) R42.1 R44.2 X34.1
CC1: C38.2 IC6.24(CC1) X30.1 ; port CC1
CC2: C39.2 IC6.25(CC2) X31.1 ; port CC2
ERP_EN: IC6.7(GPIO2) ; port ERP_EN
LDO_1V5: C35.2 IC6.4(LDO_1V5) X27.1
PP_EN: D19.A Q8.D R48.1 X25.1 ; port PP_EN
SCL: IC6.16(I2Cc_SCL) IC8.6(SCL) R46.1 X29.1 ; port SCL
SDA: IC6.15(I2Cc_SDA) IC8.5(SDA) R45.1 R53.1 X28.1 ; port SDA
VBUS_LV: C36.2 IC6.26(VBUS) IC6.27(VBUS) ; port VBUS_LV
NetD20_K: D20.K R59.1
NetIC6_20: IC6.20(POWER_PATH_EN) Q7.G
NetQ7_D: Q7.D Q8.G R47.1

Not connected (* = marked no-connect by the designer): IC6 5(GPIO0) 6(GPIO1) 8(I2Ct_SDA) 9(I2Ct_SCL) 10(nI2Ct_IRQ) 13(GPIO11) 17(nI2Cc_IRQ) 18(GPIO3) 21(NC) 22(GPIO4) 23(GPIO5) 30(GPIO7) 31(GPIO6)

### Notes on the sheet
- (near X26) 3v3 LDO
- (near X27) 1V5 LDO
- (near X25) PP enable.

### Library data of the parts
C33-C35 C37 C43 = CL10A106MA8NRNC: as C10 on sheet Charger
C36 = CL10A105KB8NNNC: as C25 on sheet Power distribution
C38 C39 = CL10B221KB8NNNC: Cap 220pF 50V 0603 X7R; Manufacturer: Samsung
D19 = PSC-1608U52GC-G4: as D12 on sheet Charger
D20 = Diode LED Green: Generic green LED symbol
IC6 = TPS26750SRSMR: USB PD IC EPR 240W; Manufacturer: Texas Instruments
IC8 = CAT24C512WI-GT3: EEPROM SOIC-8; Manufacturer: OnSemi
Q7 Q8 = 2N7002: nMOS 60V 115mA SOT-23; Manufacturer: Jiangsu Changjing Electronics Technology Co., Ltd.
R41 R44 = 0603WAF4700T5E: Res 470R 0603 1% 100mW 75V; Manufacturer: Uni-Royal
R42 R43 R53 = 0603WAF1003T5E: Res 100k 0603 1% 100mW 75V; Manufacturer: Uni-Royal
R45-R48 R59 = 0603WAF1002T5E: as R26 on sheet Charger
X25-X31 X33 X34 = ZX-PZ1.27-1-2PZZ: as X3 on sheet Charger

## Sheet USB protection.SchDoc
size A3; SheetNumber: 7; SheetTotal: 7
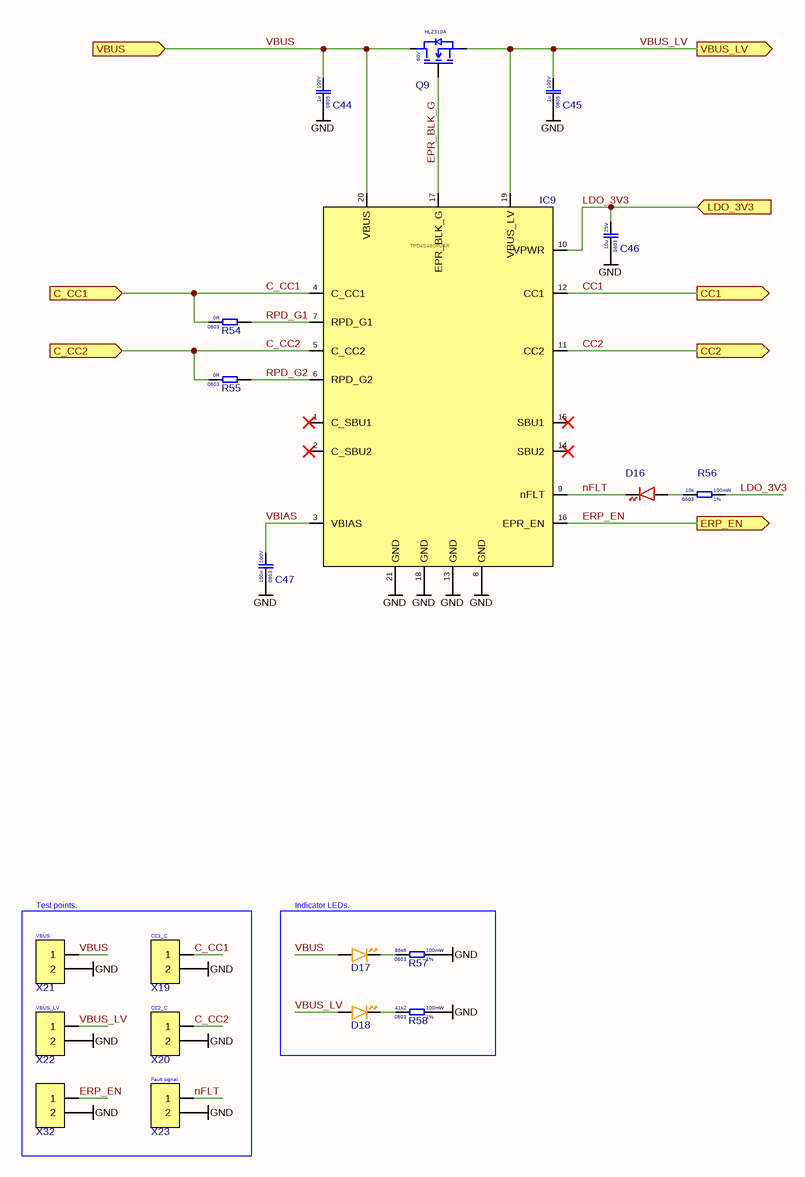
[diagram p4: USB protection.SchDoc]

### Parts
C44  Voltage Rating: 100V  Case Code (Imperial): 0805  Capacitance: 1u  [Cap_0805]  (hidden comment: CC0805KKX7R0BB105)
C45  Voltage Rating: 100V  Case Code (Imperial): 0805  Capacitance: 1u  [Cap_0805]  (hidden comment: CC0805KKX7R0BB105)
C46  Voltage Rating: 25V  Case Code (Imperial): 0603  Capacitance: 10u  [CAP 0603]  (hidden comment: CL10A106MA8NRNC)
C47  Voltage Rating: 100V  Case Code (Imperial): 0603  Capacitance: 100n  [CAP 0603]  (hidden comment: CC0603KRX7R0BB104)
D16  XL-1608SURC-06  [DIODE_0603]  (value not drawn)
D17  XL-1608UOC-06  [DIODE_0603]  (value not drawn)
D18  XL-1608UOC-06  [DIODE_0603]  (value not drawn)
IC9  TPD4S480RUKR  [WQFN (20)]
Q9  Voltage: 60V  [SOT-23 GSD]  (hidden comment: HL2310A)
R54  Resistance: 0R  Case Code (Imperial): 0603  [RES_0603]  (hidden comment: 0603WAF0000T5E)
R55  Resistance: 0R  Case Code (Imperial): 0603  [RES_0603]  (hidden comment: 0603WAF0000T5E)
R56  Resistance Tolerance: 1%  Resistance: 10k  Power Rating: 100mW  Case Code (Imperial): 0603  [RES_0603]  (hidden comment: 0603WAF1002T5E)
R57  Resistance Tolerance: 1%  Resistance: 86k6  Power Rating: 100mW  Case Code (Imperial): 0603  [RES_0603]  (hidden comment: 0603WAF8662T5E)
R58  Resistance Tolerance: 1%  Resistance: 41k2  Power Rating: 100mW  Case Code (Imperial): 0603  [RES_0603]  (hidden comment: 0603WAF4122T5E)
X19  ZX-PZ1.27-1-2PZZ  [Pin header 1x2 1.27mmP THT Vertical]  (value not drawn)
X20  ZX-PZ1.27-1-2PZZ  [Pin header 1x2 1.27mmP THT Vertical]  (value not drawn)
X21  ZX-PZ1.27-1-2PZZ  [Pin header 1x2 1.27mmP THT Vertical]  (value not drawn)
X22  ZX-PZ1.27-1-2PZZ  [Pin header 1x2 1.27mmP THT Vertical]  (value not drawn)
X23  ZX-PZ1.27-1-2PZZ  [Pin header 1x2 1.27mmP THT Vertical]  (value not drawn)
X32  ZX-PZ1.27-1-2PZZ  [Pin header 1x2 1.27mmP THT Vertical]  (value not drawn)

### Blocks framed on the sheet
Test points.: X19-X23 X32
Indicator LEDs.: D17 D18 R57 R58

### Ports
C_CC1 (in), C_CC2 (in), CC1 (out, see Arhitecture[3B], USB PD[2C]), CC2 (out, see Arhitecture[3B], USB PD[2C]), ERP_EN (out, see Arhitecture[3B], USB PD[6B]), LDO_3V3 (in, see Arhitecture[3B], USB PD[3C]), VBUS (in, see Arhitecture[2B], Power path switch[3B]), VBUS_LV (out, see Arhitecture[3B], USB PD[2B])

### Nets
GND: C44.1 C45.1 C46.1 C47.1 IC9.8(GND) IC9.13(GND) IC9.18(GND) IC9.21(GND) R57.2 R58.2 X19.2 X20.2 X21.2 X22.2 X23.2 X32.2
LDO_3V3: C46.2 IC9.10(VPWR) R56.2 ; port LDO_3V3
C_CC1: IC9.4(C_CC1) R54.1 X19.1 ; port C_CC1
C_CC2: IC9.5(C_CC2) R55.1 X20.1 ; port C_CC2
CC1: IC9.12(CC1) ; port CC1
CC2: IC9.11(CC2) ; port CC2
EPR_BLK_G: IC9.17(EPR_BLK_G) Q9.G
ERP_EN: IC9.16(EPR_EN) X32.1 ; port ERP_EN
nFLT: D16.K IC9.9(nFLT) X23.1
RPD_G1: IC9.7(RPD_G1) R54.2
RPD_G2: IC9.6(RPD_G2) R55.2
VBIAS: C47.2 IC9.3(VBIAS)
VBUS: C44.2 D17.A IC9.20(VBUS) Q9.D X21.1 ; port VBUS
VBUS_LV: C45.2 D18.A IC9.19(VBUS_LV) Q9.S X22.1 ; port VBUS_LV
NetD16_A: D16.A R56.1
NetD17_K: D17.K R57.1
NetD18_K: D18.K R58.1

Not connected (* = marked no-connect by the designer): IC9 1(C_SBU1)* 2(C_SBU2)* 14(SBU2)* 15(SBU1)*

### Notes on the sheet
- (near X21) VBUS
- (near X19) CC1_C
- (near X22) VBUS_LV
- (near X20) CC2_C
- (near X23) Fault signal.

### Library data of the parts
C44 C45 = CC0805KKX7R0BB105: Cap 1uF 100V 0805 X7R; Manufacturer: Yageo
C46 = CL10A106MA8NRNC: as C10 on sheet Charger
C47 = CC0603KRX7R0BB104: as C12 on sheet Charger
D16 = XL-1608SURC-06: as D1 on sheet Arhitecture
D17 D18 = XL-1608UOC-06: as D10 on sheet Charger
IC9 = TPD4S480RUKR: USB PD protection IC; Manufacturer: Texas Instruments
Q9 = HL2310A: nMOS 60V 3A SOT-23; Manufacturer: hongjiacheng
R54 R55 = 0603WAF0000T5E: as R21 on sheet Charger
R56 = 0603WAF1002T5E: as R26 on sheet Charger
R57 = 0603WAF8662T5E: Res 86k6 0603 1% 100mW 75V; Manufacturer: Uni-Royal
R58 = 0603WAF4122T5E: Res 41k2 0603 1% 100mW 75V; Manufacturer: Uni-Royal
X19-X23 X32 = ZX-PZ1.27-1-2PZZ: as X3 on sheet Charger

## Sheet Battery level indicator.SchDoc
size A3; SheetNumber: 3; SheetTotal: 7
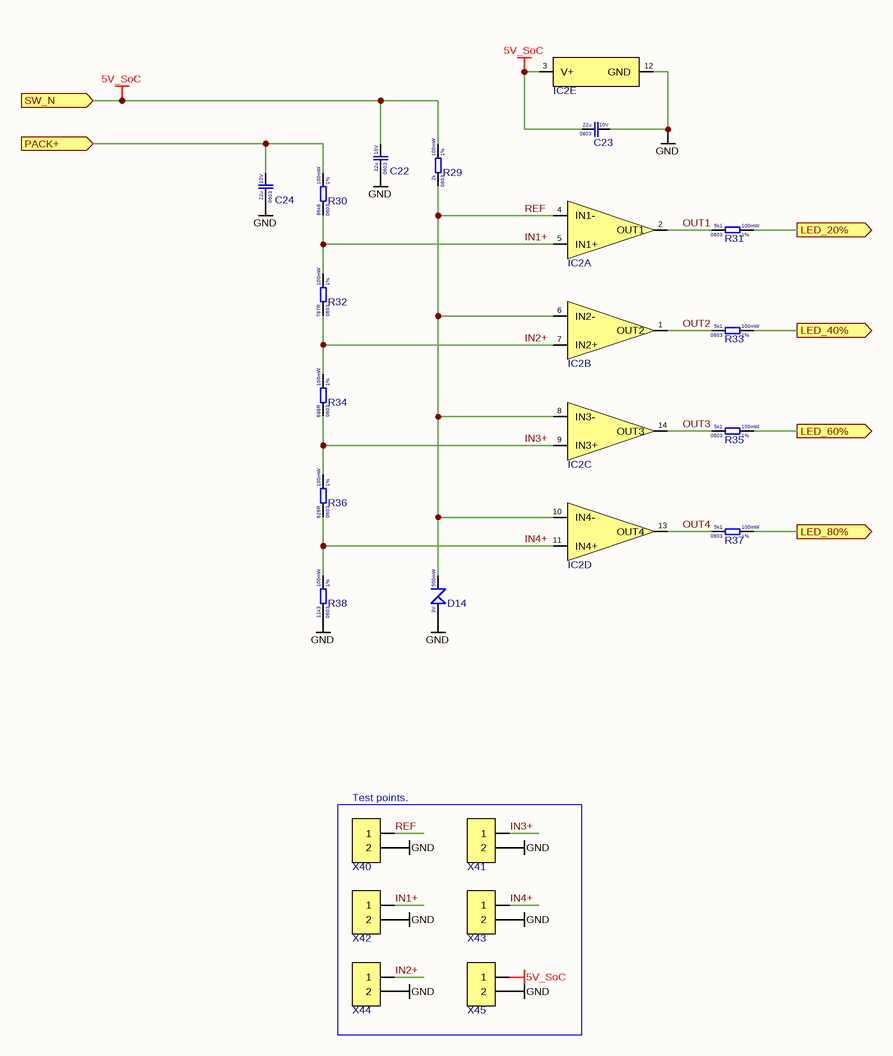
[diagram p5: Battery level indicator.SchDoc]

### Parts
C22  Voltage Rating: 10V  Case Code (Imperial): 0603  Capacitance: 22u  [CAP 0603]  (hidden comment: CGA0603X5R226M100JT)
C23  Voltage Rating: 10V  Case Code (Imperial): 0603  Capacitance: 22u  [CAP 0603]  (hidden comment: CGA0603X5R226M100JT)
C24  Voltage Rating: 10V  Case Code (Imperial): 0603  Capacitance: 22u  [CAP 0603]  (hidden comment: CGA0603X5R226M100JT)
D14  Power Rating: 500mW  Reverse Voltage: 3V  [SOD-123]  (hidden comment: BZT52C3V0)
IC2  LM339LVPWR  [TSSOP-14]  (value not drawn)  (parts A,B,C,D,E of 5)
R29  Resistance Tolerance: 1%  Resistance: 2k  Power Rating: 100mW  Case Code (Imperial): 0603  [RES_0603]  (hidden comment: 0603WAF2001T5E)
R30  Resistance Tolerance: 1%  Resistance: 86k6  Power Rating: 100mW  Case Code (Imperial): 0603  [RES_0603]  (hidden comment: 0603WAF8662T5E)
R31  Resistance Tolerance: 1%  Resistance: 5k1  Power Rating: 100mW  Case Code (Imperial): 0603  [RES_0603]  (hidden comment: 0603WAF5101T5E)
R32  Resistance Tolerance: 1%  Resistance: 787R  Power Rating: 100mW  Case Code (Imperial): 0603  [RES_0603]  (hidden comment: FRC0603F7870TS)
R33  Resistance Tolerance: 1%  Resistance: 5k1  Power Rating: 100mW  Case Code (Imperial): 0603  [RES_0603]  (hidden comment: 0603WAF5101T5E)
R34  Resistance Tolerance: 1%  Resistance: 698R  Power Rating: 100mW  Case Code (Imperial): 0603  [RES_0603]  (hidden comment: RC0603FR-07698RL)
R35  Resistance Tolerance: 1%  Resistance: 5k1  Power Rating: 100mW  Case Code (Imperial): 0603  [RES_0603]  (hidden comment: 0603WAF5101T5E)
R36  Resistance Tolerance: 1%  Resistance: 626R  Power Rating: 100mW  Case Code (Imperial): 0603  [RES_0603]  (hidden comment: RT0603BRD07626RL)
R37  Resistance Tolerance: 1%  Resistance: 5k1  Power Rating: 100mW  Case Code (Imperial): 0603  [RES_0603]  (hidden comment: 0603WAF5101T5E)
R38  Resistance Tolerance: 1%  Resistance: 11k3  Power Rating: 100mW  Case Code (Imperial): 0603  [RES_0603]  (hidden comment: FRC0603F1132TS)
X40  ZX-PZ1.27-1-2PZZ  [Pin header 1x2 1.27mmP THT Vertical]  (value not drawn)
X41  ZX-PZ1.27-1-2PZZ  [Pin header 1x2 1.27mmP THT Vertical]  (value not drawn)
X42  ZX-PZ1.27-1-2PZZ  [Pin header 1x2 1.27mmP THT Vertical]  (value not drawn)
X43  ZX-PZ1.27-1-2PZZ  [Pin header 1x2 1.27mmP THT Vertical]  (value not drawn)
X44  ZX-PZ1.27-1-2PZZ  [Pin header 1x2 1.27mmP THT Vertical]  (value not drawn)
X45  ZX-PZ1.27-1-2PZZ  [Pin header 1x2 1.27mmP THT Vertical]  (value not drawn)

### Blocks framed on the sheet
Test points.: X40-X45

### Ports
LED_20% (out, see Arhitecture[8C]), LED_40% (out, see Arhitecture[8C]), LED_60% (out, see Arhitecture[8C]), LED_80% (out, see Arhitecture[8D]), PACK+ (in, see Arhitecture[7C], Charger[8A], Power distribution[3B]), SW_N (in, see Arhitecture[7D])

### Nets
5V_SoC: C22.2 C23.1 IC2.3(V+) R29.2 X45.1 ; port SW_N
GND: C22.1 C23.2 C24.1 D14.A IC2.12(GND) R38.1 X40.2 X41.2 X42.2 X43.2 X44.2 X45.2
IN1+: IC2.5(IN1+) R30.1 R32.2 X42.1
IN2+: IC2.7(IN2+) R32.1 R34.2 X44.1
IN3+: IC2.9(IN3+) R34.1 R36.2 X41.1
IN4+: IC2.11(IN4+) R36.1 R38.2 X43.1
OUT1: IC2.2(OUT1) R31.1
OUT2: IC2.1(OUT2) R33.1
OUT3: IC2.14(OUT3) R35.1
OUT4: IC2.13(OUT4) R37.1
PACK+: C24.2 R30.2 ; port PACK+
REF: D14.K IC2.4(IN1-) IC2.6(IN2-) IC2.8(IN3-) IC2.10(IN4-) R29.1 X40.1
NetD1_A: R31.2 ; port LED_20%
NetD2_A: R33.2 ; port LED_40%
NetD3_A: R35.2 ; port LED_60%
NetD4_A: R37.2 ; port LED_80%

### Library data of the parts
C22-C24 = CGA0603X5R226M100JT: Cap 22uF 10V 0603 X5R; Manufacturer: HRE
D14 = BZT52C3V0: as D9 on sheet Charger
IC2 = LM339LVPWR: Comparator Quad 1.65~5.5V TSSOP-14; Manufacturer: Texas Instruments
R29 = 0603WAF2001T5E: Res 2k 0603 1% 100mW 75V; Manufacturer: Uni-Royal
R30 = 0603WAF8662T5E: as R57 on sheet USB protection
R31 R33 R35 R37 = 0603WAF5101T5E: Res 5k1 0603 1% 100mW 75V; Manufacturer: Uni-Royal
R32 = FRC0603F7870TS: Res 787R 0603 1% 100mW 75V; Manufacturer: FOJAN
R34 = RC0603FR-07698RL: Res 698R 0603 1% 100mW 75V; Manufacturer: YAGEO
R36 = RT0603BRD07626RL: Res 626R 0603 1% 100mW 75V; Manufacturer: YAGEO
R38 = FRC0603F1132TS: Res 11k3 0603 1% 100mW 75V; Manufacturer: Fojan
X40-X45 = ZX-PZ1.27-1-2PZZ: as X3 on sheet Charger

## Sheet Power path switch.SchDoc
size A3; SheetNumber: 6; SheetTotal: 7
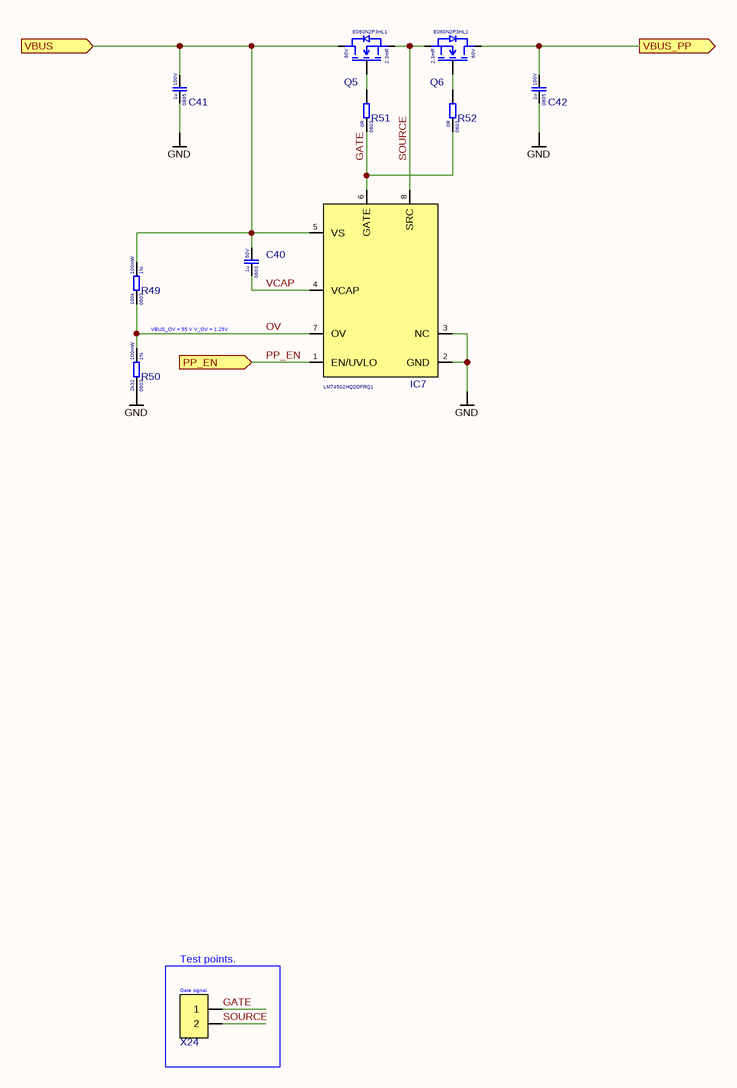
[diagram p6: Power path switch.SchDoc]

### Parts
C40  Voltage Rating: 50V  Case Code (Imperial): 0603  Capacitance: 1u  [CAP 0603]  (hidden comment: CL10A105KB8NNNC)
C41  Voltage Rating: 100V  Case Code (Imperial): 0805  Capacitance: 1u  [Cap_0805]  (hidden comment: CC0805KKX7R0BB105)
C42  Voltage Rating: 100V  Case Code (Imperial): 0805  Capacitance: 1u  [Cap_0805]  (hidden comment: CC0805KKX7R0BB105)
IC7  LM74502HQDDFRQ1  [SOT-23-8]
Q5  Rds: 2.3mR  Voltage: 60V  [DFN-8 (5x6)]  (hidden comment: E060N2P3HL1)
Q6  Rds: 2.3mR  Voltage: 60V  [DFN-8 (5x6)]  (hidden comment: E060N2P3HL1)
R49  Resistance Tolerance: 1%  Resistance: 100k  Power Rating: 100mW  Case Code (Imperial): 0603  [RES_0603]  (hidden comment: 0603WAF1003T5E)
R50  Resistance Tolerance: 1%  Resistance: 2k32  Power Rating: 100mW  Case Code (Imperial): 0603  [RES_0603]  (hidden comment: FRC0603F2321TS)
R51  Resistance: 0R  Case Code (Imperial): 0603  [RES_0603]  (hidden comment: 0603WAF0000T5E)
R52  Resistance: 0R  Case Code (Imperial): 0603  [RES_0603]  (hidden comment: 0603WAF0000T5E)
X24  ZX-PZ1.27-1-2PZZ  [Pin header 1x2 1.27mmP THT Vertical]  (value not drawn)

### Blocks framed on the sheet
Test points.: X24

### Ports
PP_EN (in, see Arhitecture[4A], USB PD[6A]), VBUS (in, see Arhitecture[3A], USB protection[3B]), VBUS_PP (out, see Arhitecture[4A])

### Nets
GND: C41.1 C42.1 IC7.2(GND) IC7.3(NC) R50.1
GATE: IC7.6(GATE) R51.1 R52.1 X24.1
OV: IC7.7(OV) R49.1 R50.2
PP_EN: IC7.1(EN/UVLO) ; port PP_EN
SOURCE: IC7.8(SRC) Q5.S Q6.S X24.2
V_CHG_IN: C42.2 Q6.D ; port VBUS_PP
VBUS: C40.2 C41.2 IC7.5(VS) Q5.D R49.2 ; port VBUS
VCAP: C40.1 IC7.4(VCAP)
NetQ5_G: Q5.G R51.2
NetQ6_G: Q6.G R52.2

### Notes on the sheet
- VBUS_OV = 55 V V_OV = 1.25V
- (near X24) Gate signal.

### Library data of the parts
C40 = CL10A105KB8NNNC: as C25 on sheet Power distribution
C41 C42 = CC0805KKX7R0BB105: as C44 on sheet USB protection
IC7 = LM74502HQDDFRQ1: High-side switch controller IC 3.2~65V Reverse polarity protection; Manufacturer: Texas Instruments
Q5 Q6 = E060N2P3HL1: Nmos 60V 180A 2.3mR PDFN5x6-8; Manufacturer: Existar
R49 = 0603WAF1003T5E: as R42 on sheet USB PD
R50 = FRC0603F2321TS: Res 2k32 0603 1% 100mW 75V; Manufacturer: Uni-Royal
R51 R52 = 0603WAF0000T5E: as R21 on sheet Charger
X24 = ZX-PZ1.27-1-2PZZ: as X3 on sheet Charger

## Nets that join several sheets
3V3: Power distribution (C32.2 D23.A IC5.2 X37.1), USB PD (C33.2 IC6.32)
5V: Arhitecture (SW1.1 SW1.2), Power distribution (C30.2 D22.A IC4.1 X36.1), USB PD (C37.2 IC6.28 IC6.29)
5V_SoC: Arhitecture (SW1.3 SW1.4), Battery level indicator (5 pins)
12V: Charger (D8.A), Power distribution (9 pins)
GND: Arhitecture (11 pins), Charger (47 pins), Power distribution (20 pins), USB PD (33 pins), USB protection (16 pins), Battery level indicator (12 pins), Power path switch (5 pins)
LDO_3V3: USB PD (13 pins), USB protection (C46.2 IC9.10 R56.2)
C_CC1: Arhitecture (X1.A5), USB protection (IC9.4 R54.1 X19.1)
C_CC2: Arhitecture (X1.B5), USB protection (IC9.5 R55.1 X20.1)
CC1: USB PD (C38.2 IC6.24 X30.1), USB protection (IC9.12)
CC2: USB PD (C39.2 IC6.25 X31.1), USB protection (IC9.11)
ERP_EN: USB PD (IC6.7), USB protection (IC9.16 X32.1)
NetD1_A: Arhitecture (D1.A), Battery level indicator (R31.2)
NetD2_A: Arhitecture (D2.A), Battery level indicator (R33.2)
NetD3_A: Arhitecture (D3.A), Battery level indicator (R35.2)
NetD4_A: Arhitecture (D4.A), Battery level indicator (R37.2)
PACK+: Arhitecture (MH1.1 SW2.2), Charger (5 pins), Power distribution (C26.2 C27.2 IC3.4 IC3.5), Battery level indicator (C24.2 R30.2)
PP_EN: USB PD (D19.A Q8.D R48.1 X25.1), Power path switch (IC7.1)
SCL: Arhitecture (X2.2), Charger (R21.1 X7.1), USB PD (IC6.16 IC8.6 R46.1 X29.1)
SDA: Arhitecture (X2.4), Charger (R22.1 X12.1), USB PD (5 pins)
V_CHG_IN: Charger (8 pins), Power path switch (C42.2 Q6.D)
VBUS: Arhitecture (X1.A4 X1.A9 X1.B4 X1.B9), USB protection (5 pins), Power path switch (5 pins)
VBUS_LV: USB PD (C36.2 IC6.26 IC6.27), USB protection (5 pins)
